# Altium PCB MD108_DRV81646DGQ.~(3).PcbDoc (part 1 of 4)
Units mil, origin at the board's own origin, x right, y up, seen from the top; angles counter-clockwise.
Board outline 6002 x 2931.52 mil, 4 copper layers (Top Layer, Mid-Layer 1, Mid-Layer 2, Bottom Layer), stack 92.712 mil thick; 255 components, 141 nets, 784 pads, 239 vias.
Unrouted connection lines stored in the file: 111.
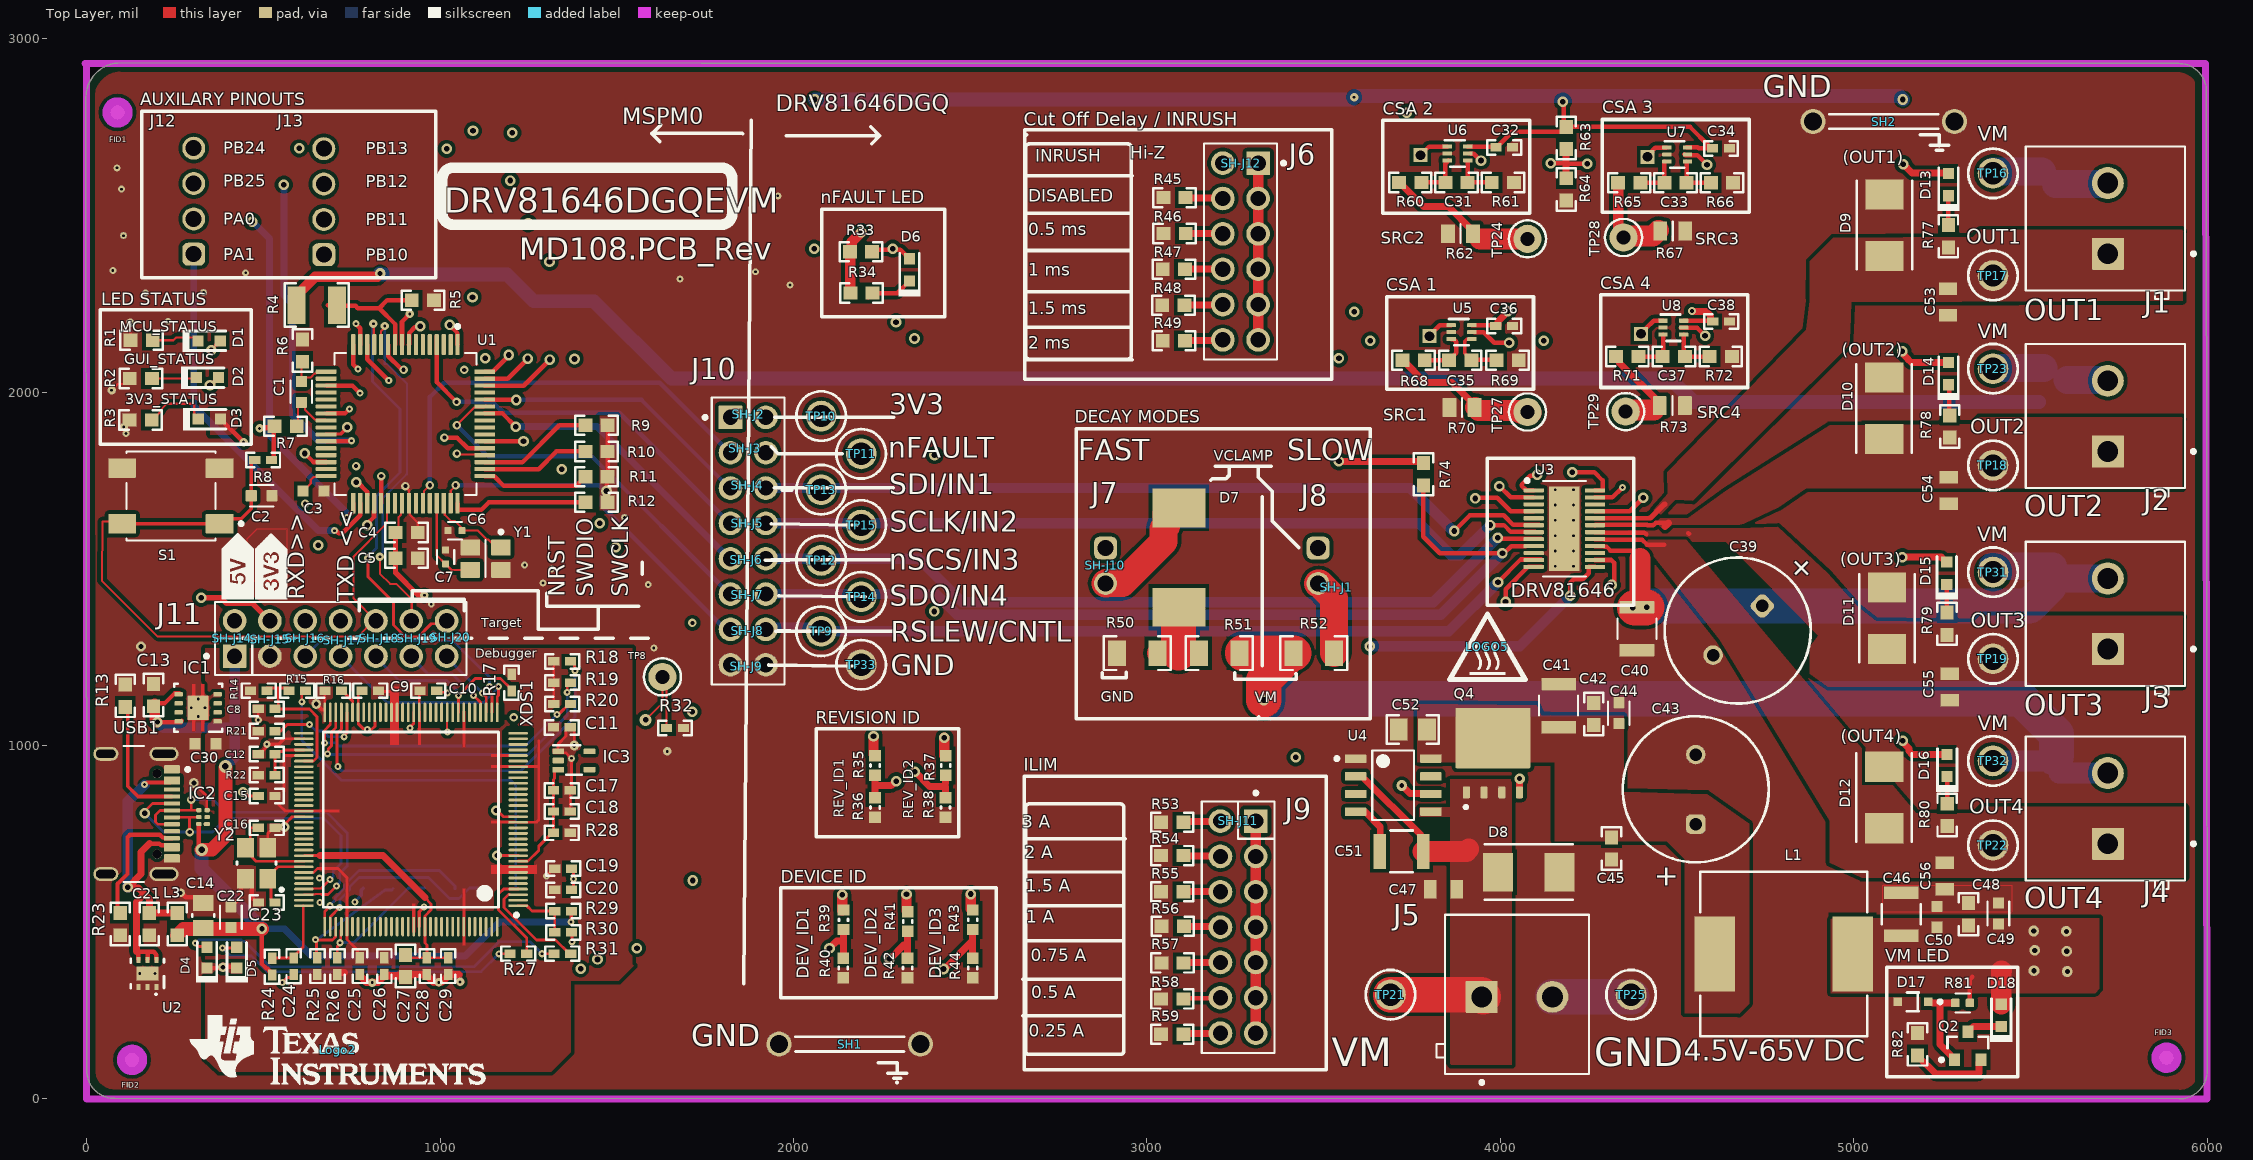
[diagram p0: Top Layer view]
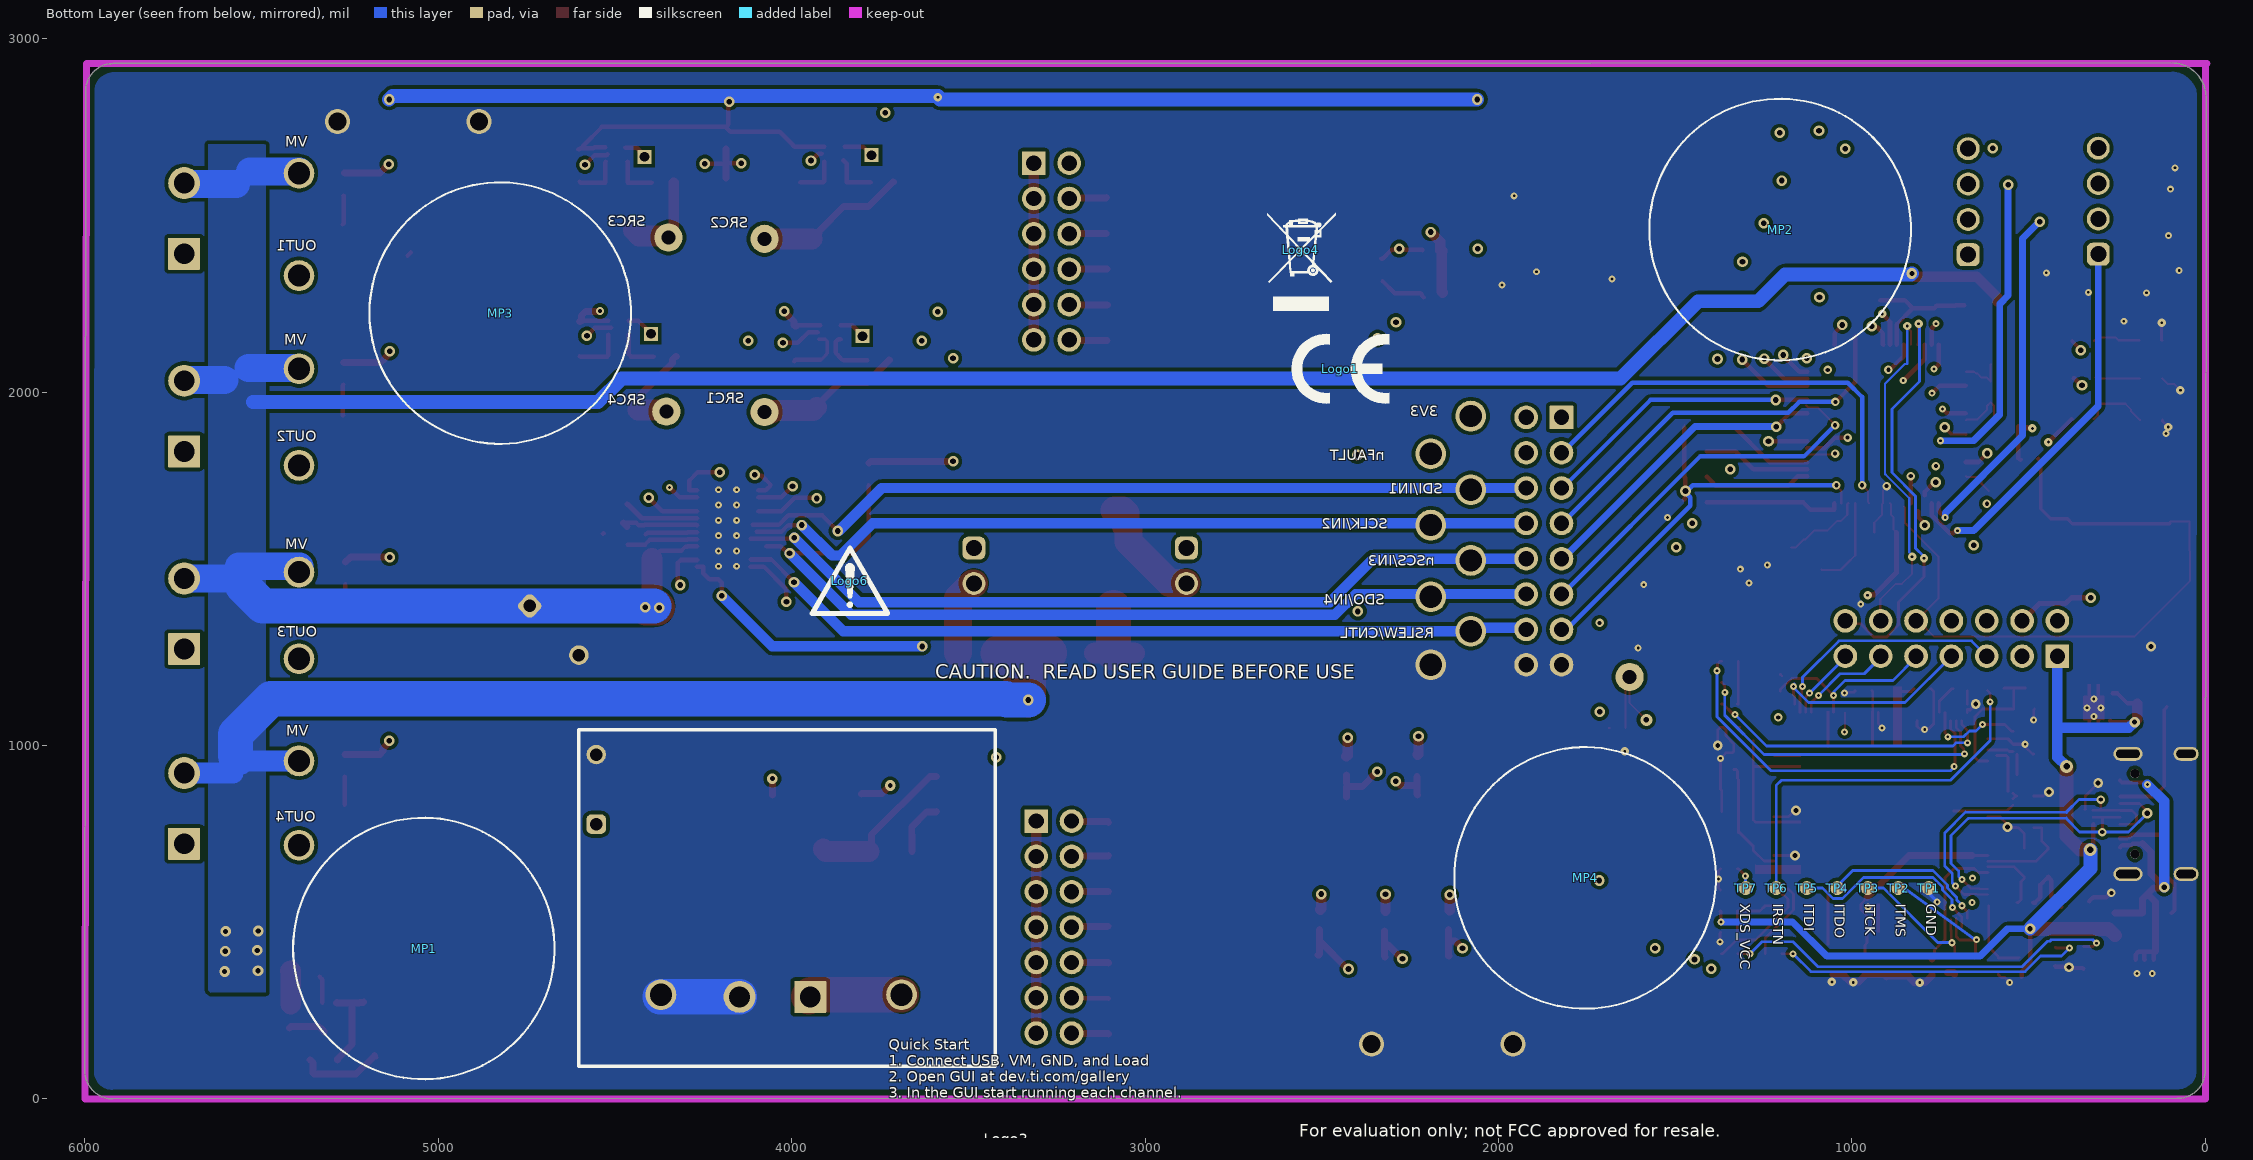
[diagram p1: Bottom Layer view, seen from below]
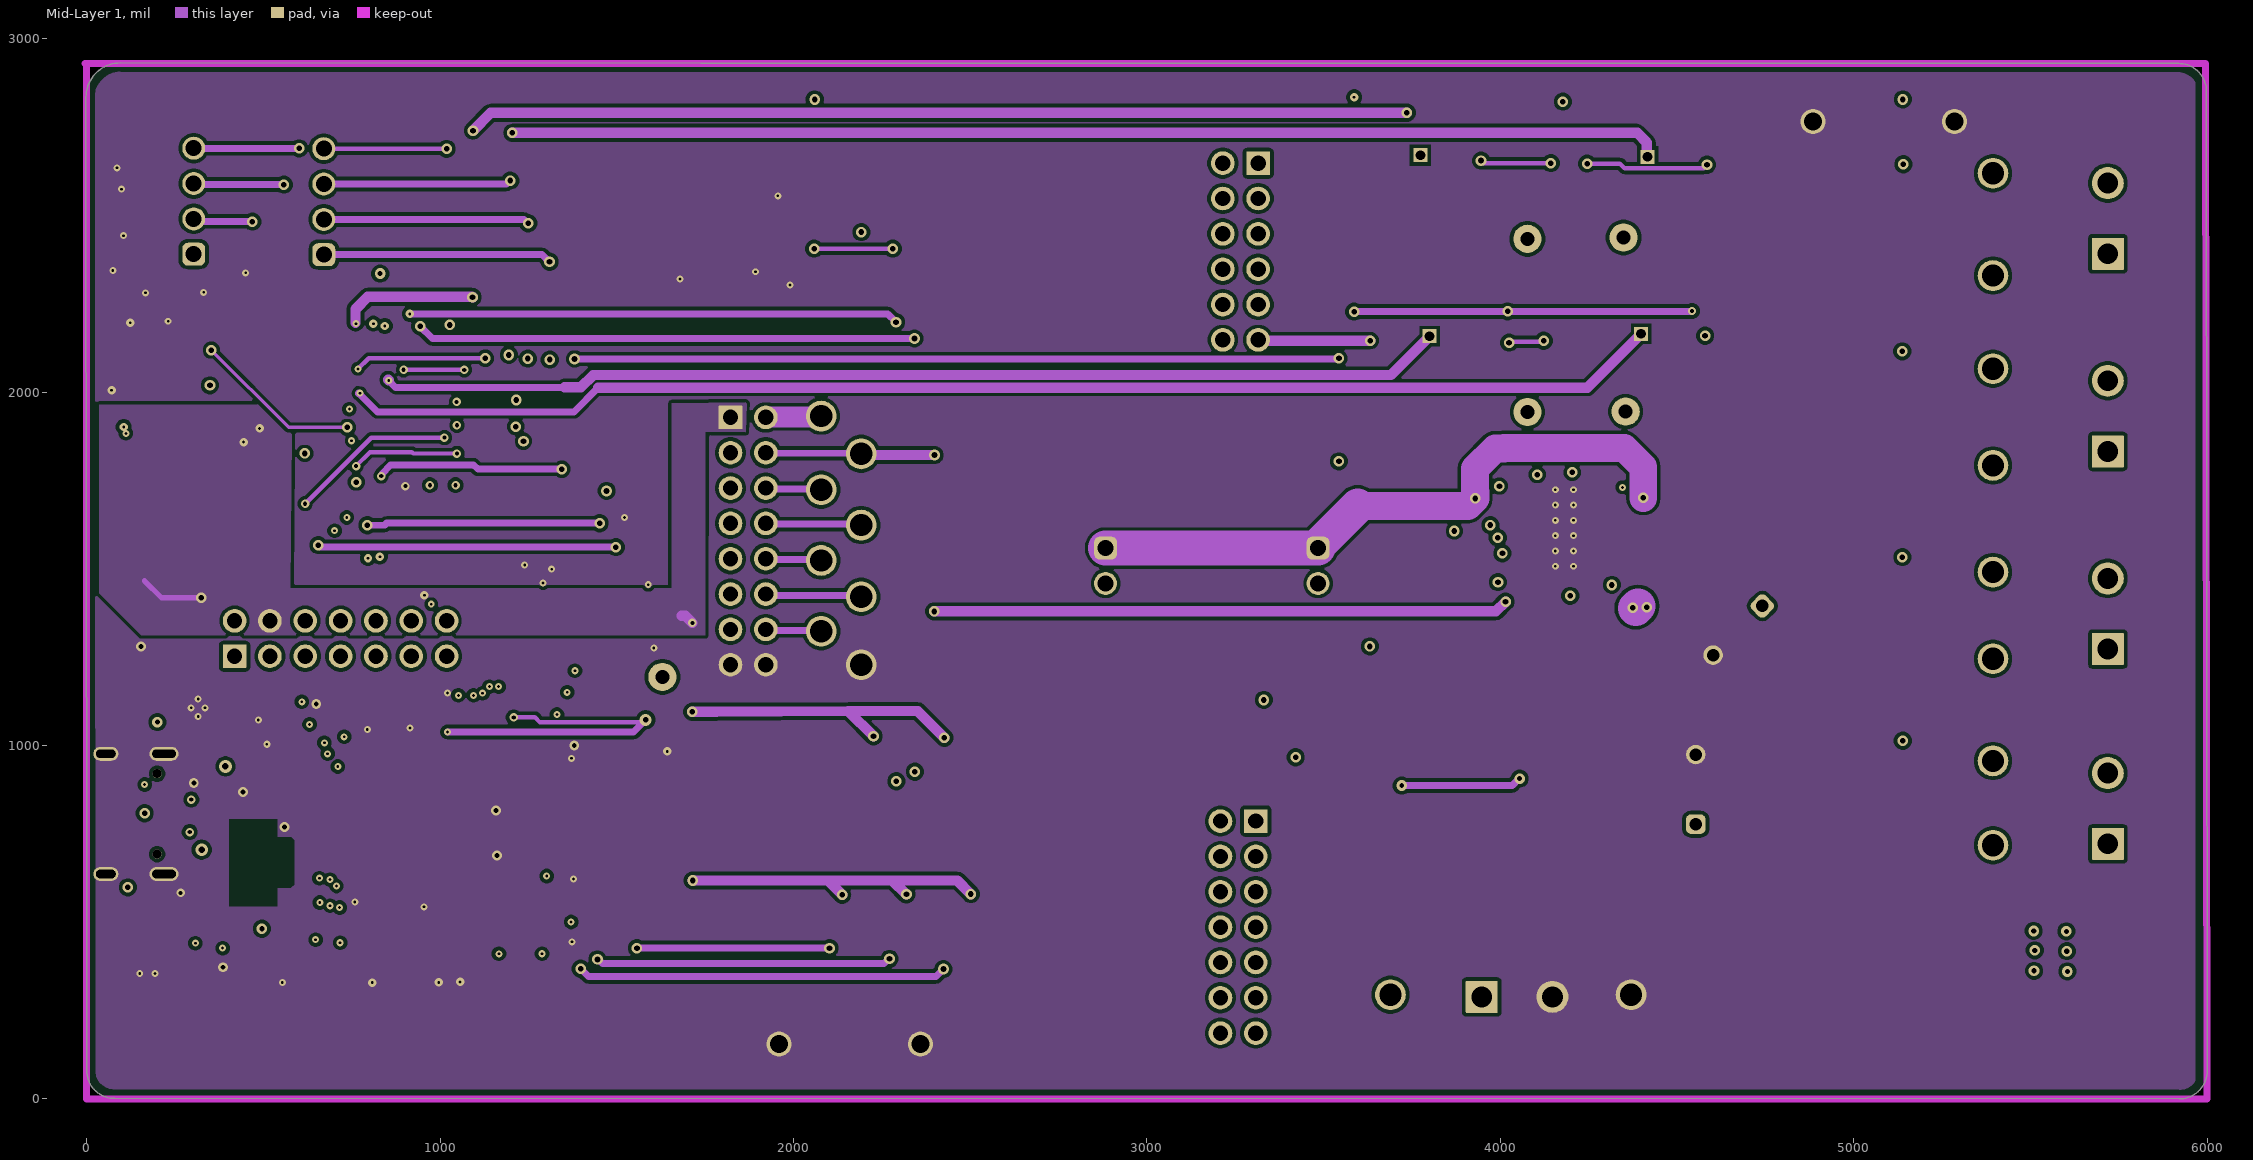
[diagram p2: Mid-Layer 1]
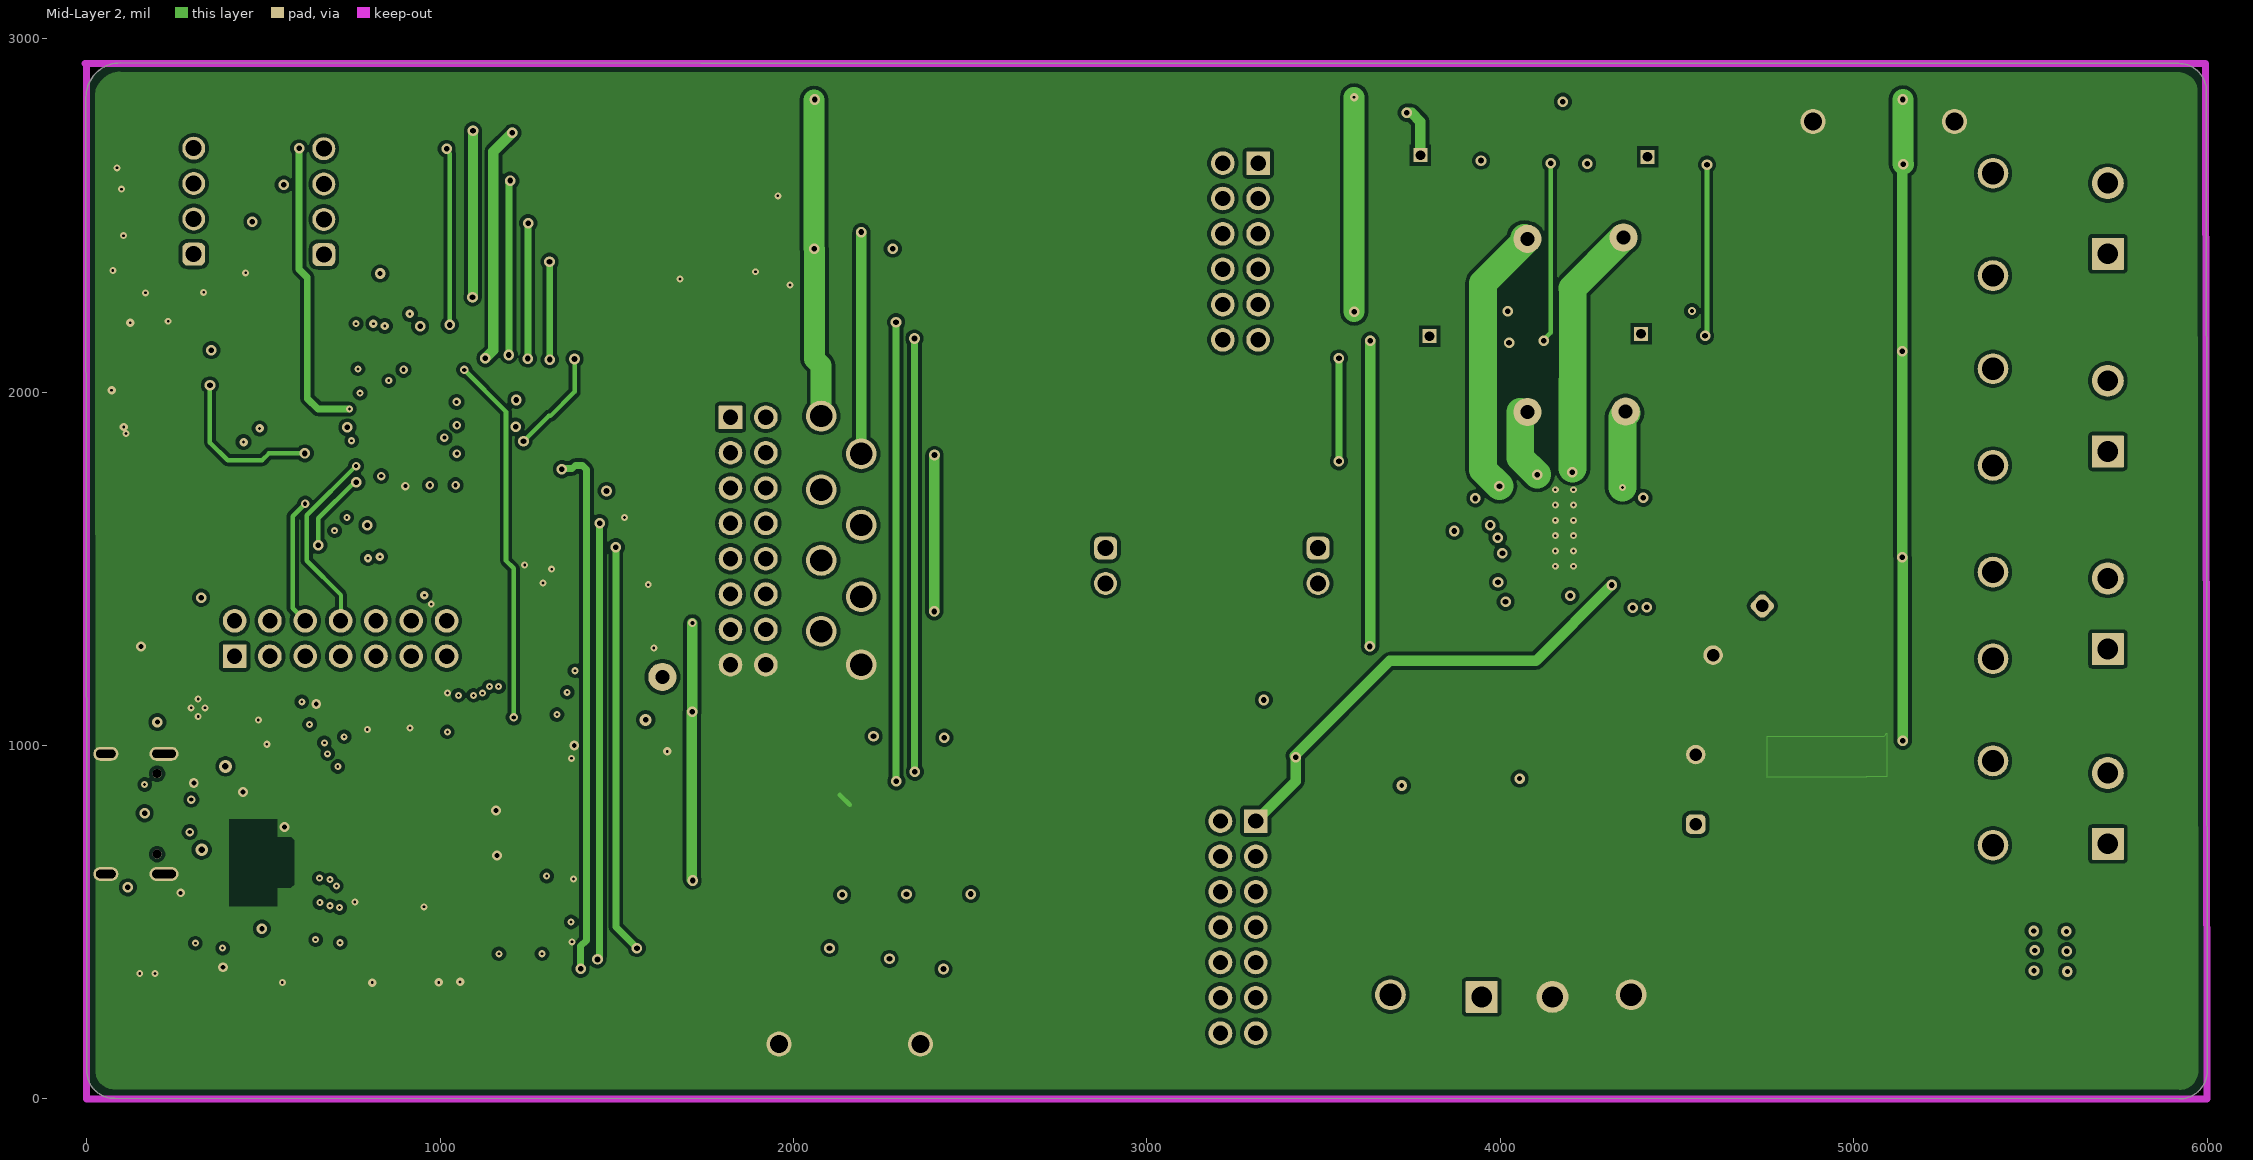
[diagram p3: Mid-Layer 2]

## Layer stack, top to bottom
Top Solder: solder mask 0.4, Solder Resist, Dk 3.5
Top Layer: signal copper 2.7559
Dielectric1: core 59.2, FR-4 High Tg, Dk 4.8
Mid-Layer 1: signal copper 1.4
Dielectric2: dielectric 12.6, FR-4, Dk 4.8
Mid-Layer 2: signal copper 1.4
Dielectric3: dielectric 12.6, FR-4, Dk 4.8
Bottom Layer: signal copper 2.7559
Bottom Solder: solder mask 0.4, Solder Resist, Dk 3.5

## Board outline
0,613.39 0,675.71 -2,2516.61 -2,2834.26 cw(c95.27,2834.26) 95.27,2931.53 1737.96,2930 5919.26,2930 cw(c5919.26,2851.26) 5998,2851.26 6000,78.76 cw(c5921.26,78.76) 5921.26,0.02 78.74,1.26 cw(c78.74,80) 0,80

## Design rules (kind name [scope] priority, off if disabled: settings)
AcuteAngle [All] p1: minimum=4.50000000000000E+0001 checktracksonly=FALSE
AssemblyTestPointUsage [All] p1: valid=2
BoardOutlineClearance BoardOutlineClearance_MountingHoles [OnCopper and InComponentClass('Mounting Holes')] p1: gap=15 ignorepadtopadclearanceinfootprint=FALSE
BoardOutlineClearance BoardOutlineClearance_Poly [OnCopper and IsPoly] p2: gap=25 ignorepadtopadclearanceinfootprint=FALSE
BoardOutlineClearance [OnCopper and Not InComponentClass('Logo') and not InComponentClass('FiducialMark') and not InRegion(1000,500,4000,800) and not InPoly] p3: gap=15 ignorepadtopadclearanceinfootprint=FALSE
Clearance Clearance_Keepouts [((IsTrack Or IsArc) And Not InPoly) And IsFree and IsKeepOut vs ((IsTrack Or IsArc) And Not InPoly) And IsFree and IsKeepOut] p1: gap=0 ignorepadtopadclearanceinfootprint=FALSE
Clearance Clearance_Poly [InPolygon] p2: gap=10 ignorepadtopadclearanceinfootprint=TRUE
Clearance Clearance_FiducialMark [IsKeepOut and InComponentClass('FiducialMark') vs IsPad and InComponentClass('FiducialMark')] p3: gap=0 ignorepadtopadclearanceinfootprint=TRUE
Clearance [All] p4: gap=6 ignorepadtopadclearanceinfootprint=TRUE
ComponentClearance ComponentClearance_Shunt [InComponentClass('Header') vs InComponentClass('Shunt')] p1: gap=0 collisioncheckmode=3 verticalgap=0 showdistances=FALSE
ComponentClearance ComponentClearance_PI_FILTER_R75 [InComponent('R75') vs InComponent('L1')] p2: gap=0 collisioncheckmode=3 verticalgap=0 showdistances=FALSE
ComponentClearance ComponentClearance_PI_FILTER_R66 [InComponent('R66') vs InComponent('L1')] p3: gap=0 collisioncheckmode=3 verticalgap=0 showdistances=FALSE
ComponentClearance ComponentClearance_CANL_Choke [InComponent('L2') vs InComponent('R71')] p4: gap=0 collisioncheckmode=3 verticalgap=0 showdistances=FALSE
ComponentClearance ComponentClearance_CANH_Choke [InComponent('L2') vs InComponent('R68')] p5: gap=0 collisioncheckmode=3 verticalgap=0 showdistances=FALSE
ComponentClearance ComponentClearance_MountingHoles_FiducialMarks [InComponentClass('Mounting Holes') vs InComponentClass('FiducialMark')] p6: gap=50 collisioncheckmode=3 verticalgap=10 showdistances=FALSE
ComponentClearance ComponentClearance_Logo [InComponentClass('Logo')] p7: gap=30 collisioncheckmode=3 verticalgap=10 showdistances=FALSE
ComponentClearance ComponentClearance_ScrewToNut [(HasFootprint('NY PMS 440 0025 PH')) vs (HasFootprint('Keystone_1902C'))] p8: gap=5 collisioncheckmode=3 verticalgap=10 showdistances=FALSE
ComponentClearance ComponentClearance_MountingHoles [InComponentClass('Mounting Holes')] p9: gap=100 collisioncheckmode=3 verticalgap=100000 showdistances=FALSE
ComponentClearance ComponentClearance_SmallPassives [HasFootprint('0201*') or HasFootprint('0402*') or HasFootprint('0508') or HasFootprint('0603*') or HasFootprint('0612') or HasFootprint('0805*') or HasFootprint('0815*') or HasFootprint('0830*') or HasFootprint('1206*') or HasFootprint('1210*') or HasFootprint('1808*') or HasFootprint('1812*') or HasFootprint('1825*') or HasFootprint('2010*') or HasFootprint('2220*') or HasFootprint('2225*') or HasFootprint('2512*') or HasFootprint('2728*') or HasFootprint('3518*') vs HasFootprint('0201*') or HasFootprint('0402*') or HasFootprint('0508') or HasFootprint('0603*') or HasFootprint('0612') or HasFootprint('0805*') or HasFootprint('0815*') or HasFootprint('0830*') or HasFootprint('1206*') or HasFootprint('1210*') or HasFootprint('1808*') or HasFootprint('1812*') or HasFootprint('1825*') or HasFootprint('2010*') or HasFootprint('2220*') or HasFootprint('2225*') or HasFootprint('2512*') or HasFootprint('2728*') or HasFootprint('3518*')] p10: gap=14.96 collisioncheckmode=3 verticalgap=10 showdistances=FALSE
ComponentClearance ComponentClearance_THtoSMT [IsThruComponent vs IsSMTComponent] p11: gap=30 collisioncheckmode=3 verticalgap=30 showdistances=FALSE
ComponentClearance ComponentClearance_THtoTH [IsThruComponent vs IsThruComponent] p12: gap=20 collisioncheckmode=3 verticalgap=30 showdistances=FALSE
ComponentClearance [All] p13: gap=20 collisioncheckmode=3 verticalgap=10 showdistances=FALSE
DiffPairsRouting [All] p1: maxlimit=100 minlimit=10 mostfreqgap=10 toplayer_minwidth=6 toplayer_maxwidth=15 toplayer_prefwidth=10 midlayer1_minwidth=6 midlayer1_maxwidth=15 midlayer1_prefwidth=10 midlayer2_minwidth=6 midlayer2_maxwidth=15 midlayer2_prefwidth=10 bottomlayer_minwidth=6 bottomlayer_maxwidth=15 bottomlayer_prefwidth=10 maxuncoupledlength=1000
FabricationTestPointUsage TestPointUsage [All] p1: valid=2 allowmultiple=FALSE
FabricationTestpoint Testpoint [All] p1: side=3 testpointundercomponent=TRUE minsize=40 maxsize=100 preferedsize=60 minholesize=0 maxholesize=40 preferedholesize=32 testpointgrid=1 allowsidetop=TRUE allowsidebottom=TRUE usegrid=TRUE gridtolerance=0.01
FanoutControl Fanout_LCC [IsLCC] p1: bgadir=Out bgaviamode=Centered fanoutstyle=Auto fanoutdirection=Alternating viagrid=1 // Fanout_LCC (Default Rule)
FanoutControl Fanout_BGA [IsBGA] p2: bgadir=Out bgaviamode=Centered fanoutstyle=Auto fanoutdirection=Alternating viagrid=1 // Fanout_BGA (Default Rule)
FanoutControl Fanout_Default [All] p4: bgadir=Out bgaviamode=Centered fanoutstyle=Auto fanoutdirection=Alternating viagrid=1 // Fanout_Default (Default Rule)
FanoutControl Fanout_Small [(CompPinCount < 5)] p5: bgadir=Out bgaviamode=Centered fanoutstyle=Auto fanoutdirection=OutThenIn viagrid=1 // Fanout_Small (Default Rule)
HoleSize [All] p1: absolutevalues=TRUE maxlimit=251 minlimit=7.87 maxpercent=80.000 minpercent=20.000
MinimumAnnularRing MinimumAnnularRing_ThermalPadVias [IsVia and InAnyComponent] p1: minimumring=5.91
MinimumAnnularRing [All] p2: minimumring=5.91
MinimumSolderMaskSliver MinimumSolderMaskSliver_Logo [InComponentClass('Logo') vs InComponentClass('Logo')] p1: minsoldermaskwidth=0.7
MinimumSolderMaskSliver [All] p2: minsoldermaskwidth=3.94
PlaneClearance [All] p1: clearance=10
PlaneConnect [All] p1: planeconnectstyle=Direct reliefexpansion=10 reliefentries=4 reliefconductorwidth=10 reliefairgap=10
PolygonConnect [All] p1: connectstyle=Direct reliefconductorwidth=10 reliefentries=4 polygonreliefangle="90 Angle" airgapwidth=10
RoutingVias ThermalPadVias [IsVia and InAnyComponent] p1: holewidth=7.87 width=19.68 viastyle="Through Hole" minholewidth=7.87 minwidth=19.68 maxholewidth=12.99 maxwidth=23.62
RoutingVias [All] p2: holewidth=16 width=34 viastyle="Through Hole" minholewidth=7.87 minwidth=19.68 maxholewidth=236.22 maxwidth=236.22
SilkToBoardRegionClearance [Not ((IsComment or IsDesignator) And (Hide <> 'False')) and not InRegion(1000,500,4000,800)] p1:
SilkToSilkClearance SilkToSilkClearance_Pb-FreeLogo [(HasFootprint('Pb-Free_Overlay_Medium') OR HasFootprint('Pb-Free_Overlay_Small')) vs (HasFootprint('Pb-Free_Overlay_Medium') OR HasFootprint('Pb-Free_Overlay_Small'))] p1: silktosilkclearance=0
SilkToSilkClearance [All] p2: silktosilkclearance=3.94
SilkToSolderMaskClearance SilkToComponentPadClearance [(IsPad or IsFill or IsRegion) and InAnycomponent] p1: minsilkscreentomaskgap=5 clearancetoexposedcopper=TRUE
SilkToSolderMaskClearance "Silk to Solder Mask Opening" [All] p2: minsilkscreentomaskgap=3.94 clearancetoexposedcopper=FALSE
SolderMaskExpansion [All] p1: expansion=1.97 istentingtop=FALSE
UnRoutedNet [All] p1: checkbadconnections=TRUE
Width [All] p1: maxlimit=100 minlimit=6 preferedwidth=10 checkconnectedcopper=TRUE
13 further rules are at their usual default settings.

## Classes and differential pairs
component class MD108_DRV81646_ADC: C31 C32 C33 C34 C35 C36 C37 C38 R60 R61 R63 R64 R65 R66 R68 R69 R71 R72 U5 U6 U7 U8
component class MD108_DRV81646__Hardware: !PCB1 FID1 FID2 FID3 Logo1 Logo2 Logo3 Logo4 LOGO5 Logo6 MP1 MP2 MP3 MP4 ZZ1 ZZ2 ZZ3 ZZ4
component class MD108_DRV81646: 15 C39 C40 C41 C42 C43 C44 C45 C46 C47 C48 C49 C50 C51 C52 C53 C54 C55 C56 D7 D8 D9 D10 D11 D12 D13 D14 D15 D16 J1 J2 J3 J4 J5 J6 J7 J8 J9 L1 L? Q4 R45 R46 R47 R48 R49 R50 R51 R52 R53 R54 R55 R56 R57 R58 R59 R62 R67 R70 R73 R77 R78 R79 R80 SH1 SH2 SH-J1 SH-J10 SH-J11 SH-J12 TP16 TP17 TP18 TP19 TP21 TP22 TP23 TP24 TP25 TP27 TP28 TP29 TP31 TP32 U3 U4
component class MD108_DRV81646_XDS110: C8 C9 C10 C11 C12 C13 C14 C15 C16 C17 C18 C19 C20 C21 C22 C23 C24 C25 C26 C27 C28 C29 C30 D4 D5 IC1 IC2 IC3 J11 L3 R13 R14 R15 R16 R17 R18 R19 R20 R21 R22 R23 R24 R25 R26 R27 R28 R29 R30 R31 SH-J14 SH-J15 SH-J16 SH-J17 SH-J18 SH-J19 SH-J20 TP1 TP2 TP3 TP4 TP5 TP6 TP7 U2 USB1 XDS1 Y2
component class MD108_DRV81646_M0: 20 C1 C2 C3 C4 C5 C6 C7 D1 D2 D3 D6 D17 D18 J10 J12 J13 Q2 R1 R2 R3 R4 R5 R6 R7 R8 R9 R10 R11 R12 R32 R33 R34 R35 R36 R37 R38 R39 R40 R41 R42 R43 R44 R74 R81 R82 S1 SH-J2 SH-J3 SH-J4 SH-J5 SH-J6 SH-J7 SH-J8 SH-J9 TP8 TP9 TP10 TP11 TP12 TP13 TP14 TP15 TP33 U1 Y1
differential pair XDS_USB_D: +XDS_USB_D_P -XDS_USB_D_N

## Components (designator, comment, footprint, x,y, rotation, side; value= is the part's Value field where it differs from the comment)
C1 "885012206126" FP-885012206126_0603-MFG 607.41,2000.55 r270 top value=1µF
C2 "885012206065" FP-885012206065_0603-MFG 495.05,1706.73 r0 top value=10nF
C3 "885012206075R" WCAP-CSGP_0603_L1.6W0.8H0.8_Reflow 642.05,1720 r180 top value=470nF
C4 "885012206095" 0603 905.33,1602.89 r0 top value=0.1uF
C5 "GRM188R61E106KA73D" 0603 905.33,1530 r0 top value=10uF
C6 "885012005057" FP-885012005057_0402-MFG 1042.39,1607.9 r0 top value=22pF
C7 "885012005057" FP-885012005057_0402-MFG 1015.46,1533.37 r270 top value=22pF
C8 "GRM155R70J104KA01D" 0402 509,1103.54 r180 top value=0.1uF
C9 "GRM155R71E103KA01D" 0402 802.37,1154.97 r180 top value=0.01uF
C10 "GRM155R71E103KA01D" 0402 966.81,1154.97 r0 top value=0.01uF
C11 "GRM155R71E103KA01D" 0402 1344.73,1051.55 r0 top value=0.01uF
C12 "GRM155R70J104KA01D" 0402 509,975.59 r180 top value=0.1uF
C13 "885012206052" 0603 189.03,1142.53 r90 top value=1uF
C14 "885012107014" 0805_150 329.91,519.42 r90 top value=10uF
C15 "GRM155R71E103KA01D" 0402 509,857.18 r180 top value=0.01uF
C16 "GRM1555C1H120JA01D" 0402 509,767.24 r0 top value=12pF
C17 "GRM155R70J104KA01D" 0402 1344.73,873 r0 top value=0.1uF
C18 "GRM155R71E103KA01D" 0402 1344.73,813.04 r0 top value=0.01uF
C19 "C1005X5R1E105K050BC" 0402 1348.19,651.39 r0 top value=1uF
C20 "GRM155R70J104KA01D" 0402 1348.19,591.43 r0 top value=0.1uF
C21 "885012206089" 0603 177.25,494.57 r270 top value=0.01uF
C22 "885012206095" FP-885012206095_0603-MFG 408.25,514.37 r90 top value=100nF
C23 "GRM1555C1H120JA01D" 0402 509.41,555.64 r180 top value=12pF
C24 "GRM155R70J104KA01D" 0402 585.83,375.41 r270 top value=0.1uF
C25 "GRM155R70J104KA01D" 0402 773.12,375.96 r270 top value=0.1uF
C26 "C1005X5R1E105K050BC" 0402 842,375.96 r270 top value=1uF
C27 "C0603C225K8PACTU" 0603 902.34,375.96 r270 top value=2.2uF
C28 "GRM155R70J104KA01D" 0402 962.68,375.96 r270 top value=0.1uF
C29 "C1005X5R1E105K050BC" 0402 1023.03,375.96 r270 top value=1uF
C30 "885012206027" WCAP-CSGP_0603_L1.6W0.8H0.8_Reflow 336.05,1004.81 r0 top
C31 "885012206046" 0603 3876.1,2593.45 r0 top value=0.1uF
C32 "885012105001" 0402 4011.06,2692.55 r180 top value=0.1uF
C33 "885012206046" 0603 4495.61,2592.62 r0 top value=0.1uF
C34 "885012105001" 0402 4624.49,2689.56 r180 top value=0.1uF
C35 "885012206046" 0603 3886.74,2090.28 r0 top value=0.1uF
C36 "885012105001" 0402 4010.62,2187.16 r180 top value=0.1uF
C37 "885012206046" 0603 4491.03,2100.6 r0 top value=0.1uF
C38 "885012105001" 0402 4624.72,2199.69 r180 top value=0.1uF
C39 "860040875002" WCAP-ATUL_D10H12.5 4671.79,1325.24 r45 top
C40 "885012209069" FP-885012209069_1210-MFG 4386.53,1330.37 r90 top value=1µF
C41 "885012209069" FP-885012209069_1210-MFG 4165.2,1112.91 r270 top value=1µF
C42 "885012206114" 0603 4264.44,1089.02 r270 top value=0.01uF
C43 "860040875004" WCAP-ATUL_D10H20 4553.07,876 r270 top
C44 "885012206120" FP-885012206120_0603-MFG 4335.44,1091.54 r270 top value=100nF
C45 "06031C102KAT2A" 0603 4314.68,708.6 r270 top value=1000pF
C46 "885012209069" FP-885012209069_1210-MFG 5134.6,522.48 r270 top value=1µF
C47 "885012207124" WCAP-CSGP_0805_L2W1.25H0.8_Reflow 3839.36,593.25 r0 top
C48 "885012206114" 0603 5324.84,522.48 r270 top value=0.01uF
C49 "885012206120" FP-885012206120_0603-MFG 5409.61,524.35 r270 top value=100nF
C50 "885012206108" WCAP-CSGP_0603_L1.6W0.8H0.8_Reflow 5236.17,515.12 r270 top
C51 "885382209002" WCAP-CSST_1210_L3.2W2.5H2.5 3720.55,700.46 r0 top
C52 "C2012X7S2A105K125AB" 0805_HV 3752.39,1045.6 r180 top value=1uF
C53 "885012207124" WCAP-CSGP_0805_L2W1.25H0.8_Reflow 5267.21,2255.09 r90 top
C54 "885012207124" WCAP-CSGP_0805_L2W1.25H0.8_Reflow 5268.84,1721.22 r90 top
C55 "885012207124" WCAP-CSGP_0805_L2W1.25H0.8_Reflow 5271.77,1165.87 r90 top
C56 "885012207124" WCAP-CSGP_0805_L2W1.25H0.8_Reflow 5257.62,630.82 r90 top
D1 "150060VS75000" WL-SMCW_GREEN 346.32,2145.05 r0 top value=Green
D2 "150060VS75000" WL-SMCW_GREEN 341.42,2040.9 r0 top value=Green
D3 "150060VS75000" WL-SMCW_GREEN 347.02,1923.54 r0 top value=Green
D4 "LTST-C190KRKT" LED_LTST-C190_Red 340.61,399.58 r270 top value=Red
D5 "LTST-C190GKT" LED_LTST-C190 424.61,399.58 r270 top value=Green
D6 "150060RS75000" WL-SMCW_RED 2328.08,2345.76 r90 top value=Red
D7 "SMCJ33CA" SMC_Bi 3090.32,1531.78 r270 top value=33V
D8 "SMBJ70CA-13-F" SMB-Bi 4080.57,641.49 r180 top value=70V
D9 "SMBJ33CA-13-F" SMB-Bi 5087.03,2472.52 r270 top value=33V
D10 "SMBJ33CA-13-F" SMB-Bi 5086.38,1954.04 r270 top value=33V
D11 "SMBJ33CA-13-F" SMB-Bi 5093.88,1359.86 r270 top value=33V
D12 "SMBJ33CA-13-F" SMB-Bi 5086.38,852.82 r270 top value=33V
D13 "150060VS75000" WL-SMCW_GREEN 5268.29,2587.26 r90 top value=Green
D14 "150060VS75000" WL-SMCW_GREEN 5268.47,2052.36 r90 top value=Green
D15 "150060VS75000" WL-SMCW_GREEN 5263.45,1487.42 r90 top value=Green
D16 "150060VS75000" WL-SMCW_GREEN 5264.42,943.52 r90 top value=Green
D17 "BZX84J-B4V7,115" FP-SOD323F-MFG 5167.62,274.75 r180 top
D18 "150060VS75000" WL-SMCW_GREEN 5417.46,236.37 r90 top value=Green
FID1 "Fiducial" Fiducial10-20 87.36,2791.28 r0 top
FID2 "Fiducial" Fiducial10-20 128.19,110.46 r0 top
FID3 "Fiducial" Fiducial10-20 5884.93,116.59 r0 top
IC1 "TPS73533DRBT" DRB0008A 315.39,1106.58 r180 top
IC2 "TPD4E004DRYR" DRY0006A 329.16,797.26 r180 top
IC3 "LM4040C25IDCKR" DCK0005A_N 1378.61,957.57 r0 top
J1 "691236510002" FP-691236510002_HHR2-MFG 5712.13,2479.6 r90 top
J2 "691236510002" FP-691236510002_HHR2-MFG 5712.13,1920.23 r90 top
J3 "691236510002" FP-691236510002_HHR2-MFG 5712.13,1360.87 r90 top
J4 "691236510002" FP-691236510002_HHR2-MFG 5712.13,810.06 r90 top
J5 "691236510002" FP-691236510002_HHR2-MFG 4035.69,295.59 r0 top
J6 "61301221121" FP-61301221121_HDR12-MFG 3264.82,2397.78 r270 top
J7 "61300211121" WURTH_61300211121 2883.02,1508.7 r270 top
J8 "61300211121" WURTH_61300211121 3484.34,1508.63 r270 top
J9 "61301421121" FP-61301421121_HDR14-MFG#1 3258.12,486.13 r270 top
J10 "61301621121" FP-61301621121_HDR16-MFG 1871.74,1578.5 r270 top
J11 "61301421121" FP-61301421121_HDR14-MFG#2 718.44,1302.72 r0 top locked
J12 "61300411121" WURTH_61300411121 302.88,2540.15 r90 top
J13 "61300411121" WURTH_61300411121 670.89,2538.76 r90 top
L1 "7443320100" WE-HCC_1210 4802.03,410.11 r0 top value=1uH
L3 "742863160" 0603 256.06,494.57 r270 top value="600 ohm"
Logo1 "CE Mark" CE_Mark_5mm 2447.5,2066.02 r180 bottom
Logo2 "Texas Instruments" TI_Stacked_Overlay_Small 710.1,138.81 r0 top
Logo3 "FCC disclaimer" FCC_disclaimer -705,1946.08 r90 bottom
Logo4 "WEEE logo" WEEE_Minimum 2559.23,2402.87 r180 bottom
LOGO5 "CAUTION HOT SURFACE" IEC_HotSurface_Small 3963.77,1279.84 r0 top
Logo6 "CAUTION.  READ USER GUIDE BEFORE USE" IEC_Caution_Small 3835.17,1466.27 r180 bottom
MP1 "RBS-37BK" FP-RBS-37BK_BUMPER_CYLI-MFG 5041.03,425.57 r180 bottom
MP2 "RBS-37BK" FP-RBS-37BK_BUMPER_CYLI-MFG 1203.08,2460 r180 bottom
MP3 "RBS-37BK" FP-RBS-37BK_BUMPER_CYLI-MFG 4824.79,2223.61 r180 bottom
MP4 "RBS-37BK" FP-RBS-37BK_BUMPER_CYLI-MFG 1754.91,625.3 r180 bottom
Q2 "BC846BLT1G" ONSC-SOT-23-3-318-08_V 5323.01,150.05 r90 top
Q4 "CSD19502Q5B" DNK0008A 3979.19,978.27 r90 top value=80V
R1 "RC0603JR-07330RL" 0603 155.3,2146.65 r0 top value=330
R2 "RC0603JR-07330RL" 0603 153.23,2038.49 r0 top value=330
R3 "RC0603JR-07330RL" 0603 152.54,1921.12 r0 top value=330
R4 "RC1210JR-0720KL" 1210 650.95,2246.08 r180 top value=20k
R5 "RC0603JR-071KL" 0603 951.19,2259.83 r180 top value=1.0k
R6 "Resistor" 0603 610.38,2117.27 r270 top value=0
R7 "Resistor" 0603 562.84,1903.13 r0 top value=0
R8 "CRCW040247K0JNED" 0402 498.96,1808.03 r0 top value=47k
R9 "ERJ-3GEYJ104V" 0603 1442.48,1906.07 r0 top value=100k
R10 "RC0603FR-07249KL" 0603 1442.48,1832.03 r0 top value=249k
R11 "RC0603FR-0744K2L" 0603 1442.48,1760.56 r0 top value=44.2k
R12 "RC0603FR-0714KL" 0603 1442.48,1688.28 r0 top value=14.0k
R13 "RC0603JR-075K1L" 0603 108.91,1140.63 r90 top value=5.1k
R14 "CRCW040210K0JNED" 0402 486.88,1154.97 r180 top value=10k
R15 "CRCW0402100RJNED" 0402 595.6,1154.97 r180 top value=100
R16 "CRCW04024K87FKED" 0402 697.67,1154.97 r0 top value=4.87k
R17 "ERJ-2RKF3301X" 0402 1202.57,1177.91 r90 top value=3.30k
R18 "CRCW04021K00JNED" 0402 1345.19,1238.25 r180 top value=1.0k
R19 "CRCW04021K00JNED" 0402 1345.19,1177.91 r180 top value=1.0k
R20 "CRCW04021K00JNED" 0402 1345.19,1117.57 r180 top value=1.0k
R21 "CRCW04021K00JNED" 0402 509,1040.68 r180 top value=1.0k
R22 "CRCW040251R0JNED" 0402 509,916.14 r180 top value=51
R23 "RC0603JR-075K1L" 0603 94.73,494.57 r270 top value=5.1k
R24 "CRCW0402100RJNED" 0402 524.7,374.36 r90 top value=100
R25 "CRCW040210K0JNED" 0402 652.61,375.94 r90 top value=10k
R26 "CRCW040210K0JNED" 0402 709.08,375.96 r90 top value=10k
R27 "CRCW0402470RJNED" 0402 1221.5,410.78 r0 top value=470
R28 "CRCW04021K00JNED" 0402 1344.73,753.08 r0 top value=1.0k
R29 "RC0402FR-07330KL" 0402 1348.19,531.47 r180 top value=330k
R30 "RC0402FR-07220KL" 0402 1348.19,471.51 r180 top value=220k
R31 "CRCW0402470RJNED" 0402 1346.07,410.78 r0 top value=470
R32 "CRCW040247K0JNED" 0402 1664.63,1049.62 r180 top value=47k
R33 "RC0603FR-074K99L" 0603 2190.93,2397.03 r0 top value=4.99k
R34 "RC0603JR-07330RL" 0603 2192.28,2280.1 r0 top value=330
R35 "RC0603JR-0710KL" 0603L 2230.96,943.45 r270 top value=10k
R36 "RC0603JR-0710KL" 0603L 2230.96,824.68 r270 top value=10k
R37 "RC0603JR-0710KL" 0603L 2430.64,943.45 r270 top value=10k
R38 "RC0603JR-0710KL" 0603L 2430.05,824.68 r270 top value=10k
R39 "RC0603JR-0710KL" 0603L 2141.22,506.62 r270 top value=10k
R40 "RC0603JR-0710KL" 0603L 2140.92,370.32 r270 top value=10k
R41 "RC0603JR-0710KL" 0603L 2323.2,502.09 r270 top value=10k
R42 "RC0603JR-0710KL" 0603L 2323.04,370.32 r270 top value=10k
R43 "RC0603JR-0710KL" 0603L 2506.99,506.62 r270 top value=10k
R44 "RC0603JR-0710KL" 0603L 2506.99,370.32 r270 top value=10k
R45 "RC0603FR-0710KL" 0603 3078.09,2550.3 r0 top value=10.0k
R46 "RC0603FR-0760K4L" 0603 3078.39,2449.01 r0 top value=60.4k
R47 "RC0603FR-07120KL" 0603 3076.26,2347.62 r0 top value=120k
R48 "RC0603FR-07180KL" 0603 3074.89,2246.05 r0 top value=180k
R49 "RC0603FR-07240KL" 0603 3076.26,2145.4 r0 top value=240k
R50 "CRCW12060000Z0EAHP" 1206 2972.91,1261.31 r0 top value=0
R51 "CRCW12060000Z0EAHP" 1206 3204.66,1261.31 r0 top value=0
R52 "CRCW12060000Z0EAHP" 1206 3472.19,1261.31 r180 top value=0
R53 "RC0603FR-0710KL" 0603 3071.69,782.73 r0 top value=10.0k
R54 "RC0603FR-0730KL" 0603 3071.69,688.45 r0 top value=30.0k
R55 "RC0603FR-0740K2L" 0603 3071.69,586.38 r0 top value=40.2k
R56 "RC0603FR-0760K4L" 0603 3073.17,488.58 r0 top value=60.4k
R57 "RC0603FR-0780K6L" 0603 3072.24,384.93 r0 top value=80.6k
R58 "RC0603FR-07120KL" 0603 3071.69,283.06 r0 top value=120k
R59 "RC0603FR-07240KL" 0603 3071.69,183.06 r0 top value=240k
R60 "ERJ-3GEY0R00V" 0603 3745.11,2593.39 r0 top value=0
R61 "ERJ-3GEY0R00V" 0603 4007.19,2593.45 r180 top value=0
R62 "580060720008" FP-580060720008_0805-MFG 3887.13,2448.16 r0 top value=10m
R63 "RC0603FR-07200RL" 0603 4186.49,2718.83 r90 top value=200
R64 "RC0603FR-07200RL" 0603 4186.49,2573.68 r90 top value=200
R65 "ERJ-3GEY0R00V" 0603 4364.97,2592.62 r0 top value=0
R66 "ERJ-3GEY0R00V" 0603 4627.42,2592.68 r180 top value=0
R67 "580060720008" FP-580060720008_0805-MFG 4487.92,2456.06 r180 top value=10m
R68 "ERJ-3GEY0R00V" 0603 3754.69,2090.21 r0 top value=0
R69 "ERJ-3GEY0R00V" 0603 4020.73,2090.28 r180 top value=0
R70 "580060720008" FP-580060720008_0805-MFG 3891.95,1956.14 r0 top value=10m
R71 "ERJ-3GEY0R00V" 0603 4359.37,2100.53 r0 top value=0
R72 "ERJ-3GEY0R00V" 0603 4623.9,2100.6 r180 top value=0
R73 "580060720008" FP-580060720008_0805-MFG 4486.7,1961.6 r180 top value=10m
R74 "RC0603FR-0710KL" 0603 3782.47,1767.52 r90 top value=10.0k
R77 "RC0603JR-07430RL" 0603 5267.95,2441.05 r90 top value=430
R78 "RC0603JR-07430RL" 0603 5271.63,1902.5 r90 top value=430
R79 "RC0603JR-07430RL" 0603 5263.97,1344.47 r90 top value=430
R80 "RC0603JR-07430RL" 0603 5264.42,803.75 r90 top value=430
R81 "RCC040247K0FKED" FP-RCC040247K0FKED_0402-MFG 5308.17,271.59 r0 top value=47k
R82 "RC0603FR-07470RL" 0603 5180.71,154.48 r270 top value=470
S1 "430481025816" FP-430481025816_SMT_SW_6MM2_6MM2-MFG 238.32,1706.39 r180 top
SH1 "Jumper_2p" Harwin_D3082-05 2159,154.99 r180 top
SH2 "Jumper_2p" Harwin_D3082-05 5085.01,2765.61 r180 top
SH-J1 "60900213421" Wurth_60900213421 3535.96,1448.43 r180 top
SH-J2 "60900213421" Wurth_60900213421 1871.63,1938.04 r180 top
SH-J3 "60900213421" Wurth_60900213421 1862.63,1841.54 r180 top
SH-J4 "60900213421" Wurth_60900213421 1868.77,1737.07 r180 top
SH-J5 "60900213421" Wurth_60900213421 1868.77,1629.54 r180 top
SH-J6 "60900213421" Wurth_60900213421 1865.7,1525.07 r180 top
SH-J7 "60900213421" Wurth_60900213421 1868.77,1426.75 r180 top
SH-J8 "60900213421" Wurth_60900213421 1868.77,1325.36 r180 top
SH-J9 "60900213421" Wurth_60900213421 1865.7,1223.97 r180 top
SH-J10 "60900213421" Wurth_60900213421 2882.46,1509.96 r270 top
SH-J11 "60900213421" Wurth_60900213421 3258.01,786.45 r180 top
SH-J12 "60900213421" Wurth_60900213421 3266.5,2647.22 r0 top
SH-J14 "60900213421" Wurth_60900213421 412.41,1303.85 r270 top
SH-J15 "60900213421" Wurth_60900213421 519.95,1300.78 r270 top
SH-J16 "60900213421" Wurth_60900213421 618.27,1303.85 r270 top
SH-J17 "60900213421" Wurth_60900213421 725.81,1297.71 r270 top
SH-J18 "60900213421" Wurth_60900213421 827.2,1303.85 r270 top
SH-J19 "60900213421" Wurth_60900213421 934.74,1303.85 r270 top
SH-J20 "60900213421" Wurth_60900213421 1029.98,1306.93 r270 top
TP1 "TESTPOINT" TP_SM_1MM 782.61,596.57 r180 bottom
TP2 "TESTPOINT" TP_SM_1MM 868.95,596.57 r180 bottom
TP3 "TESTPOINT" TP_SM_1MM 955.28,596.57 r180 bottom
TP4 "TESTPOINT" TP_SM_1MM 1041.61,596.57 r180 bottom
TP5 "TESTPOINT" TP_SM_1MM 1127.95,596.57 r180 bottom
TP6 "TESTPOINT" TP_SM_1MM 1214.28,596.57 r180 bottom
TP7 "TESTPOINT" TP_SM_1MM 1300.61,596.57 r180 bottom
TP8 "5002" Keystone5002 1629,1194 r90 top
TP9 "5012" Keystone5012 2078.24,1323.12 r90 top
TP10 "5013" Keystone5013 2078.24,1932.21 r90 top
TP11 "5012" Keystone5012 2191.45,1825.2 r90 top
TP12 "5012" Keystone5012 2078.24,1523.57 r90 top
TP13 "5012" Keystone5012 2078.24,1724.03 r90 top
TP14 "5012" Keystone5012 2191.45,1420.6 r90 top
TP15 "5012" Keystone5012 2191.45,1623.8 r90 top
TP16 "5010" Keystone5010 5394.16,2618.94 r270 top
TP17 "5012" Keystone5012 5394.16,2329.77 r270 top
TP18 "5012" Keystone5012 5394.16,1792.45 r270 top
TP19 "5012" Keystone5012 5394.16,1245.29 r270 top
TP21 "5010" Keystone5010 3689.25,294.92 r90 top
TP22 "5012" Keystone5012 5394.16,717.89 r270 top
TP23 "5010" Keystone5010 5394.16,2066.42 r270 top
TP24 "5002" Keystone5002 4076.86,2433.69 r90 top
TP25 "5011" Keystone5011 4370.1,294.92 r90 top
TP27 "5002" Keystone5002 4076.86,1943.72 r90 top
TP28 "5002" Keystone5002 4348.72,2437.5 r270 top
TP29 "5002" Keystone5002 4354.75,1944.92 r90 top
TP31 "5010" Keystone5010 5394.16,1490.69 r90 top
TP32 "5010" Keystone5010 5394.16,956.25 r90 top
TP33 "5011" Keystone5011 2191.45,1228.39 r90 top
U1 "MSPM0G3507SPM" PM0064A-MFG 902.05,1910 r270 top
U2 "TVS0500DRVR" DRV0006A 171.8,354.86 r90 top
U3 "DRV81646DGQ" DGQ0024A-MFG 4181.31,1613.52 r0 top
U4 "LM74700D-Q1" D0008A-MFG 3696.83,887.81 r0 top
U5 "INA185A2IDRLT" DRL0006A 3890.31,2169.82 r0 top
U6 "INA185A2IDRLT" DRL0006A 3878.92,2675.21 r0 top
U7 "INA185A2IDRLT" DRL0006A 4500.52,2672.23 r0 top
U8 "INA185A2IDRLT" DRL0006A 4489.7,2182.36 r0 top
USB1 "629722000214" FP-629722000214_CONN_USB-MFG 99.31,806.46 r270 top
XDS1 "MSP432E401YTPDTR" PDT0128A 917.61,790.57 r180 top
Y1 "X1E0000210179" FP-X1E0000210179_TSX-3225-MFG 1128.92,1528.66 r180 top
Y2 "NX3225GA-16.000M-STD-CRG-1" NDK_NX3225GA 480.69,666.88 r180 top
ZZ1 "This Assembly Note is for PCB labels only" AssemblyNoteLabel 78.04,7760 r0 top
ZZ2 "These assemblies are ESD sensitive, ESD precautions shall be observed." AssemblyNote 83,7642 r0 top
ZZ3 "These assemblies must be clean and free from flux and all contaminants. Use of no clean flux is not acceptable." AssemblyNote 82,7517 r0 top
ZZ4 "These assemblies must comply with workmanship standards IPC-A-610 Class 2, unless otherwise specified." AssemblyNote 82,7372 r0 top

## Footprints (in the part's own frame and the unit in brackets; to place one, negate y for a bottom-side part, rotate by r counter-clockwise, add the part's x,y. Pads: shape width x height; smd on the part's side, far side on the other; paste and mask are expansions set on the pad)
0402 [mm] "0402 from SM-752 data"
  rect 0.8x0.6 smd: 1(-0.6,0) 2(0.6,0)
  silkscreen extent -1.22,-0.52 1.22,0.52, body extent -0.55,-0.3 0.55,0.3, height 0.6
0603 [mm] "0603 from SM-752 data"
  rect 1x0.95 smd: 1(-0.8,0) 2(0.8,0)
  silkscreen extent -1.52,-0.69 1.52,0.69, body extent -0.87,-0.47 0.87,0.47, height 1
0603L [mm] "0603 from SM-752 data"
  rect 0.8x0.85 smd: 1(-0.7,0) 2(0.7,0)
  silkscreen extent -0.07,-0.32 0.07,0.32, body extent -0.87,-0.47 0.87,0.47, height 1
0805_150 [mm] "0805 / 1.5 mm height"
  rect 1.15x1.45 smd: 1(-0.9,0) 2(0.9,0)
  silkscreen extent -0.1,-0.8 0.1,0.8, body extent -1.1,-0.72 1.1,0.72, height 1.5
0805_HV [mil] "0805 with 30mil clearance between pads"
  rect 50x63 smd: 1(-40,0) 2(40,0)
  silkscreen extent -74,-40 74,40, body extent -43,-29 43,29, height 57
1206 [mm] "1206 from SM-752 data"
  rect 1.3x1.85 smd: 1(-1.45,0) 2(1.45,0)
  silkscreen extent -2.4,-1.21 2.4,1.21, body extent -1.7,-0.9 1.7,0.9, height 1.35
1210 [mm] "1210 from SM-752 data"
  rect 1.3x2.7 smd: 1(-1.45,0) 2(1.45,0)
  silkscreen extent -2.32,-1.57 2.32,1.57, body extent -1.7,-1.35 1.7,1.35, height 1.35
AssemblyNote [mil] "Assembly Note"
AssemblyNoteLabel [mil] "Assembly Note for PCB Labels"
CE_Mark_5mm [mil] "Minimum text height for CE Mark"
  silkscreen extent -138,-98 138,98
D0008A-MFG [mm] "Recommended Land Pattern"
  rrect17% 1.55x0.6 smd paste+0 mask+0: 1(-2.7,1.905) 2(-2.7,0.635) 3(-2.7,-0.635) 4(-2.7,-1.905) 5(2.7,-1.905) 6(2.7,-0.635) 7(2.7,0.635) 8(2.7,1.905)
  silkscreen extent -4.17,-2.5 1.5,2.5, body extent -3,-2.45 3,2.45, height 1.75
DCK0005A_N [mm] "SOT353, 5-Leads, Body 2x1.3mm, Pitch 0.65mm, Lead Span 2.1mm, IPC Medium Density"
  rrect25% 0.85x0.4 smd: 1(-1.125,0.65) 2(-1.125,0) 3(-1.125,-0.65) 4(1.125,-0.65) 5(1.125,0.65)
  silkscreen extent -1.48,-1.02 0.55,1.1, body extent -1.14,-1 1.14,1, height 0.95
DGQ0024A-MFG [mm] "Recommended Land Pattern"
  rrect33% 1.45x0.3 smd paste+0 mask+0: 1(-2.2,2.75) 2(-2.2,2.25) 3(-2.2,1.75) 4(-2.2,1.25) 5(-2.2,0.75) 6(-2.2,0.25) 7(-2.2,-0.25) 8(-2.2,-0.75) 9(-2.2,-1.25) 10(-2.2,-1.75) 11(-2.2,-2.25) 12(-2.2,-2.75) 13(2.2,-2.75) 14(2.2,-2.25) 15(2.2,-1.75) 16(2.2,-1.25) 17(2.2,-0.75) 18(2.2,-0.25) 19(2.2,0.25) 20(2.2,0.75) 21(2.2,1.25) 22(2.2,1.75) 23(2.2,2.25) 24(2.2,2.75)
  rrect5% 2.2x6.1 smd paste-1000 mask-1000: 25(0,0)
  silkscreen extent -2.8,-3.42 1.55,3.57, body extent -3.03,-3.35 3.03,3.35, height 0.25
DNK0008A [mm] "SON, 8-Leads, Body 5x6mm"
  rrect39% 0.86x0.51 smd paste-0.05 mask-0.05: 1(-2.82,1.905) 2(-2.82,0.635) 3(-2.82,-0.635) 4(-2.82,-1.905) 5(2.82,-1.905) 6(2.82,-0.635) 7(2.82,0.635) 8(2.82,1.905)
  rrect40% 0.25x0.555 on Top Solder: 9(-0.83,2.372) 9(-0.83,-2.372)
  rrect40% 0.25x0.555 on Top Paste: 9(-0.83,2.372) 9(-0.83,-2.372)
  rrect11% 0.95x1.13 on Top Paste: 9(-0.535,0) 9(-0.535,1.33) 9(-0.535,-1.33) 9(0.615,1.33) 9(0.615,0) 9(0.615,-1.33) 9(1.765,-1.33) 9(1.765,0) 9(1.765,1.33)
  rrect3% 3.58x4 on Top Solder: 9(0.75,0)
  rrect5% 4.34x5.4 smd paste-3 mask-3: 9(1.08,0)
  body extent -3.05,-2.55 3.05,2.55, height 1.06
DRB0008A [mm] "VSON-8"
  rrect32% 0.6x0.31 smd: 1(-1.4,0.975) 2(-1.4,0.325) 3(-1.4,-0.325) 4(-1.4,-0.975) 5(1.4,-0.975) 6(1.4,-0.325) 7(1.4,0.325) 8(1.4,0.975)
  rrect7% 1.5x1.75 smd paste-0.75: 9(0,0)
  Top Layer region: -0.7,-0.875 -0.49,-0.875 -0.471,-0.879 -0.455,-0.89 -0.444,-0.906 -0.44,-0.925 -0.44,-0.925 -0.44,-1.65 -0.436,-1.669 -0.425,-1.685 -0.409,-1.696 -0.39,-1.7 -0.39,-1.7 -0.26,-1.7 -0.241,-1.696 -0.225,-1.685 -0.214,-1.669 -0.21,-1.65 -0.21,-1.65 -0.21,-0.925 -0.206,-0.906 -0.195,-0.89 -0.179,-0.879 -0.16,-0.875 -0.16,-0.875 0.16,-0.875 0.179,-0.879 0.195,-0.89 0.206,-0.906 0.21,-0.925 0.21,-0.925 0.21,-1.65 0.21,-1.65 0.214,-1.669 0.225,-1.685 0.241,-1.696 0.26,-1.7 0.26,-1.7 0.39,-1.7 0.409,-1.696 0.425,-1.685 0.436,-1.669 0.44,-1.65 0.44,-1.65 0.44,-0.925 0.444,-0.906 0.455,-0.89 0.471,-0.879 0.49,-0.875 0.49,-0.875 0.7,-0.875 0.719,-0.871 0.735,-0.86 0.746,-0.844 0.75,-0.825 0.75,-0.825 0.75,0.825 0.746,0.844 0.735,0.86 0.719,0.871 0.7,0.875 0.7,0.875 0.49,0.875 0.471,0.879 0.455,0.89 0.444,0.906 0.44,0.925 0.44,0.925 0.44,1.65 0.436,1.669 0.425,1.685 0.409,1.696 0.39,1.7 0.39,1.7 0.26,1.7 0.241,1.696 0.225,1.685 0.214,1.669 0.21,1.65 0.21,1.65 0.21,1.65 0.21,0.925 0.206,0.906 0.195,0.89 0.179,0.879 0.16,0.875 0.16,0.875 -0.16,0.875 -0.179,0.879 -0.195,0.89 -0.206,0.906 -0.21,0.925 -0.21,0.925 -0.21,1.65 -0.214,1.669 -0.225,1.685 -0.241,1.696 -0.26,1.7 -0.26,1.7 -0.39,1.7 -0.409,1.696 -0.425,1.685 -0.436,1.669 -0.44,1.65 -0.44,1.65 -0.44,0.925 -0.444,0.906 -0.455,0.89 -0.471,0.879 -0.49,0.875 -0.49,0.875 -0.7,0.875 -0.719,0.871 -0.735,0.86 -0.746,0.844 -0.75,0.825 -0.75,0.825 -0.75,-0.825 -0.746,-0.844 -0.735,-0.86 -0.719,-0.871 -0.7,-0.875
  silkscreen extent -1.73,-1.73 1.73,1.73, body extent -1.5,-1.5 1.5,1.5, height 0.77
DRL0006A [mm] "SOTFL, 6-Flat Leads, Body 1.2x1.6x0.6mm, Pitch 0.5mm, TI recommended"
  rrect33% 0.67x0.3 smd: 1(-0.74,0.5) 2(-0.74,0) 3(-0.74,-0.5) 4(0.74,-0.5) 5(0.74,0) 6(0.74,0.5)
  silkscreen extent -0.9,-0.95 0.5,0.95, body extent -0.8,-0.8 0.8,0.8, height 0.61
DRV0006A [mm] "SON, 6-Leads, Body 2x2mm, Pitch 0.65mm, Thermal Pad 1.6x1mm, TI Recommended"
  rrect33% 0.45x0.3 smd: 1(-0.975,-0.65) 2(-0.975,0) 3(-0.975,0.65) 4(0.975,0.65) 5(0.975,0) 6(0.975,-0.65)
  rrect14% 1x0.7 on Top Paste: 7(0,0.45) 7(0,-0.45)
  rrect10% 1x1.6 smd paste-0.5: 7(0,0)
  silkscreen extent -1.05,-1.2 1.05,1.2, body extent -1.05,-1.05 1.05,1.05, height 0.81
DRY0006A [mm] "USON-6"
  rrect67% 0.45x0.3 smd paste-0.05 mask-0.05: 1(-0.275,0.5)
  rrect67% 0.4x0.3 smd paste-0.05 mask-0.05: 2(-0.3,0) 3(-0.3,-0.5) 4(0.3,-0.5) 5(0.3,0) 6(0.3,0.5)
  body extent -0.5,-0.72 0.5,0.73, height 0.58
FCC_disclaimer [mil]
Fiducial10-20 [mm]
  round 1 smd mask+0.5: 1(0,0)
  Top Layer keep-out circle w1.178: c0,0 r0.5
FP-61301221121_HDR12-MFG [mm]
  rrect6% 1.7x1.7 hole 1.1 paste-1000 mask+0: 1(-6.35,1.27)
  round 1.7 hole 1.1 paste-1000 mask+0: 2(-6.35,-1.27) 3(-3.81,1.27) 4(-3.81,-1.27) 5(-1.27,1.27) 6(-1.27,-1.27) 7(1.27,1.27) 8(1.27,-1.27) 9(3.81,1.27) 10(3.81,-1.27) 11(6.35,1.27) 12(6.35,-1.27)
  silkscreen extent -7.77,-2.62 7.77,3.22, body extent -7.62,-2.54 7.62,2.54, height 5.54
FP-61301421121_HDR14-MFG#1 [mm]
  rrect6% 1.7x1.7 hole 1.1 paste-1000 mask+0: 1(-7.62,1.27)
  round 1.7 hole 1.1 paste-1000 mask+0: 2(-7.62,-1.27) 3(-5.08,1.27) 4(-5.08,-1.27) 5(-2.54,1.27) 6(-2.54,-1.27) 7(0,1.27) 8(0,-1.27) 9(2.54,1.27) 10(2.54,-1.27) 11(5.08,1.27) 12(5.08,-1.27) 13(7.62,1.27) 14(7.62,-1.27)
  silkscreen extent -9.76,-2.62 9.04,2.62, body extent -8.89,-2.54 8.89,2.54, height 8.89
FP-61301421121_HDR14-MFG#2 [mm]
  rrect6% 1.7x1.7 hole 1.1 paste-1000 mask+0: 1(-7.62,-1.27)
  round 1.7 hole 1.1 paste-1000 mask+0: 2(-7.62,1.27) 3(-5.08,-1.27) 4(-5.08,1.27) 5(-2.54,-1.27) 6(-2.54,1.27) 7(0,-1.27) 8(0,1.27) 9(2.54,-1.27) 10(2.54,1.27) 11(5.08,-1.27) 12(5.08,1.27) 13(7.62,-1.27) 14(7.62,1.27)
  silkscreen extent -9.76,-2.62 9.04,2.62, body extent -9.14,-2.72 9.14,2.72, height 0.25
FP-61301621121_HDR16-MFG [mm] "Recommended Land Pattern"
  rrect6% 1.7x1.7 hole 1.1 paste-2539.97 mask+0: 1(-8.89,-1.27)
  round 1.7 hole 1.1 paste-2539.97 mask+0: 2(-8.89,1.27) 3(-6.35,-1.27) 4(-6.35,1.27) 5(-3.81,-1.27) 6(-3.81,1.27) 7(-1.27,-1.27) 8(-1.27,1.27) 9(1.27,-1.27) 10(1.27,1.27) 11(3.81,-1.27) 12(3.81,1.27) 13(6.35,-1.27) 14(6.35,1.27) 15(8.89,-1.27) 16(8.89,1.27)
  silkscreen extent -10.31,-3.22 10.31,2.62, body extent -10.16,-2.54 10.16,2.54, height 8.89
FP-430481025816_SMT_SW_6MM2_6MM2-MFG [mm]
  rrect7% 2x1.4 smd paste+0 mask+0: 1(-3.5,2) 2(3.5,2) 3(-3.5,-2) 4(3.5,-2)
  silkscreen extent -5.18,-3.2 3.2,3.2, body extent -4.6,-3.3 4.6,3.3, height 0.25
FP-580060720008_0805-MFG [mm]
  rrect10% 1x1.36 smd paste+0 mask+0: 1(-0.9,0) 2(0.9,0)
  silkscreen extent 0,-0.68 0,0.68, body extent -1.5,-0.8 1.5,0.8, height 0.25
FP-629722000214_CONN_USB-MFG [mm]
  rrect100% 1x2.1 hole 1.7 slot 0.6 at 0 deg paste-1000 mask+0: 1(-4.32,3.035) 2(4.32,3.035)
  rrect100% 1x1.8 hole 1.4 slot 0.6 at 0 deg paste-1000 mask+0: 3(-4.32,-1.145) 4(4.32,-1.145)
  rrect17% 0.6x1.15 smd paste+0 mask+0: A1-B12(-3.2,3.6) A4-B9(-2.4,3.6) A9-B4(2.4,3.6) A12-B1(3.2,3.6)
  rrect33% 0.3x1.15 smd paste+0 mask+0: A5(-1.25,3.6) A6(-0.25,3.6) A7(0.25,3.6) A8(1.25,3.6) B5(1.75,3.6) B6(0.75,3.6) B7(-0.75,3.6) B8(-1.75,3.6)
  round 0.65 hole 0.65 unplated paste-1000 mask+0: ""(-2.89,2.535) ""(2.89,2.535)
  silkscreen extent -4.89,0.13 4.89,4.86, body extent -4.99,-3.97 4.99,4.28, height 0.25
FP-691236510002_HHR2-MFG [mm]
  rrect4% 2.3x2.3 hole 1.5 paste-1000 mask+0: 1(-2.24,-0.175)
  round 2.3 hole 1.5 paste-1000 mask+0: 2(2.84,-0.175)
  silkscreen extent -5.48,-6.45 5.48,5.72, body extent -5.58,-5.82 5.58,5.82, height 0.25
FP-885012005057_0402-MFG [mm]
  rrect20% 0.5x0.5 smd paste+0 mask+0: 1(-0.5,0) 2(0.5,0)
  silkscreen extent -0.5,-0.63 0.5,0.63, body extent -0.85,-0.38 0.85,0.38, height 0.25
FP-885012206065_0603-MFG [mm]
  rrect13% 0.8x0.8 smd paste+0 mask+0: 1(-0.75,0) 2(0.75,0)
  silkscreen extent -0.85,-0.77 0.85,0.77, body extent -1.25,-0.55 1.25,0.55, height 0.25
FP-885012206095_0603-MFG [mm]
  rrect13% 0.8x0.8 smd paste+0 mask+0: 1(-0.75,0) 2(0.75,0)
  silkscreen extent -0.85,-0.77 0.85,0.77, body extent -1.25,-0.55 1.25,0.55, height 0.25
FP-885012206120_0603-MFG [mm]
  rrect13% 0.8x0.8 smd paste+0 mask+0: 1(-0.75,0) 2(0.75,0)
  silkscreen extent -0.85,-0.77 0.85,0.77, body extent -0.8,-0.4 0.8,0.4, height 0.87
FP-885012206126_0603-MFG [mm]
  rrect13% 0.8x0.8 smd paste+0 mask+0: 1(-0.75,0) 2(0.75,0)
  silkscreen extent -0.8,-0.77 0.8,0.77, body extent -1.25,-0.58 1.25,0.58, height 0.25
FP-885012209069_1210-MFG [mm]
  rrect11% 0.9x2.5 smd paste+0 mask+0: 1(-1.55,0) 2(1.55,0)
  silkscreen extent -0.72,-1.4 0.72,1.4, body extent -2.1,-1.5 2.1,1.5, height 0.25
FP-RBS-37BK_BUMPER_CYLI-MFG [mil]
  silkscreen extent -370,-370 370,370, body extent -360,-360 360,360, height 579
FP-RCC040247K0FKED_0402-MFG [mm]
  rrect17% 0.6x0.6 smd paste+0 mask+0: 1(-0.525,0) 2(0.525,0)
  silkscreen extent -0.53,-0.68 0.52,0.67, body extent -0.92,-0.4 0.92,0.4, height 0.25
FP-SOD323F-MFG [mm]
  rect 0.6x0.6 smd paste-1000 mask+0: 1(-1.1,0) 2(1.1,0)
  silkscreen extent -2.08,-0.67 0.43,0.67, body extent -1.53,-0.82 1.53,0.82, height 0.25
FP-X1E0000210179_TSX-3225-MFG [mm]
  rrect9% 1.4x1.15 smd paste+0 mask+0: 1(-1.1,-0.8) 2(1.1,-0.8) 3(1.1,0.8) 4(-1.1,0.8)
  silkscreen extent -1.22,-2.05 0,1.33, body extent -1.6,-1.25 1.6,1.25, height 0.6
Harwin_D3082-05 [mm] "Shorting Plug, 10.16mm spacing, TH"
  round 1.8 hole 1.3: 1(-5.08,0) 2(5.08,0)
  silkscreen extent -3.9,-0.53 3.9,0.53, body extent -5.6,-0.52 5.61,0.52, height 6.63
IEC_Caution_Small [mil]
  silkscreen extent -107,-93 107,92
IEC_HotSurface_Small [mil]
  silkscreen extent -107,-93 107,92
Keystone5002 [mil] "For Keystone 500x miniature loop terminals"
  round 80 hole 40: 1(0,0)
  silkscreen extent -52,-52 52,52, body extent -49,-49 49,49, height 182
Keystone5010 [mil] "Keystone Multipurpose loops"
  round 87 hole 63: 1(0,0)
  silkscreen extent -70,-70 70,70, body extent -63,-63 63,62, height 319
Keystone5011 [mil] "Keystone Multipurpose loops"
  round 87 hole 63: 1(0,0)
  silkscreen extent -70,-70 70,70, body extent -63,-63 63,62, height 319
Keystone5012 [mil] "Keystone Multipurpose loops"
  round 87 hole 63: 1(0,0)
  silkscreen extent -70,-70 70,70, body extent -63,-63 63,62, height 319
Keystone5013 [mil] "Keystone Multipurpose loops"
  round 87 hole 63: 1(0,0)
  silkscreen extent -70,-70 70,70, body extent -63,-63 63,62, height 319
LED_LTST-C190 [mm] "Lite-On"
  rect 0.8x0.8 smd: 1(-0.75,0) 2(0.75,0)
  silkscreen extent -1.1,-0.8 1.8,0.8, body extent -0.85,-0.45 0.85,0.45, height 0.9
LED_LTST-C190_Red [mm] "Lite-On"
  rect 0.8x0.8 smd: 1(-0.75,0) 2(0.75,0)
  silkscreen extent -1.1,-0.8 1.8,0.8, body extent -0.85,-0.45 0.85,0.45, height 0.9
NDK_NX3225GA [mm] "NDK"
  rect 1.2x1.4 smd: 1(-0.8,1.1) 2(-0.8,-1.1) 3(0.8,-1.1) 4(0.8,1.1)
  silkscreen extent -1.9,-0.1 1.4,2, body extent -1.3,-1.65 1.3,1.65, height 0.9
ONSC-SOT-23-3-318-08_V [mm] "SOT23, 3-Leads, Body 2.92x1.3mm, Pitch 0.95mm"
  rect 0.9x0.8 smd: 1(-1,0.95) 2(-1,-0.95) 3(1,0)
  silkscreen extent -1.12,-1.46 0.65,2.02, body extent -0.65,-1.46 0.65,1.46, height 1.11
PDT0128A [mm] "Thin QFP, 128-Leads, Body 14x14mm, Pitch 0.4mm"
  oval 1.4x0.2 smd: 1(-7.7,6.2) 2(-7.7,5.8) 3(-7.7,5.4) 4(-7.7,5) 5(-7.7,4.6) 6(-7.7,4.2) 7(-7.7,3.8) 8(-7.7,3.4) 9(-7.7,3) 10(-7.7,2.6) 11(-7.7,2.2) 12(-7.7,1.8) 13(-7.7,1.4) 14(-7.7,1) 15(-7.7,0.6) 16(-7.7,0.2) 17(-7.7,-0.2) 18(-7.7,-0.6) 19(-7.7,-1) 20(-7.7,-1.4) 21(-7.7,-1.8) 22(-7.7,-2.2) 23(-7.7,-2.6) 24(-7.7,-3) 25(-7.7,-3.4) 26(-7.7,-3.8) 27(-7.7,-4.2) 28(-7.7,-4.6) 29(-7.7,-5) 30(-7.7,-5.4) 31(-7.7,-5.8) 32(-7.7,-6.2) 65(7.7,-6.2) 66(7.7,-5.8) 67(7.7,-5.4) 68(7.7,-5) 69(7.7,-4.6) 70(7.7,-4.2) 71(7.7,-3.8) 72(7.7,-3.4) 73(7.7,-3) 74(7.7,-2.6) 75(7.7,-2.2) 76(7.7,-1.8) 77(7.7,-1.4) 78(7.7,-1) 79(7.7,-0.6) 80(7.7,-0.2) 81(7.7,0.2) 82(7.7,0.6) 83(7.7,1) 84(7.7,1.4) 85(7.7,1.8) 86(7.7,2.2) 87(7.7,2.6) 88(7.7,3) 89(7.7,3.4) 90(7.7,3.8) 91(7.7,4.2) 92(7.7,4.6) 93(7.7,5) 94(7.7,5.4) 95(7.7,5.8) 96(7.7,6.2)
  oval 0.2x1.4 smd: 33(-6.2,-7.7) 34(-5.8,-7.7) 35(-5.4,-7.7) 36(-5,-7.7) 37(-4.6,-7.7) 38(-4.2,-7.7) 39(-3.8,-7.7) 40(-3.4,-7.7) 41(-3,-7.7) 42(-2.6,-7.7) 43(-2.2,-7.7) 44(-1.8,-7.7) 45(-1.4,-7.7) 46(-1,-7.7) 47(-0.6,-7.7) 48(-0.2,-7.7) 49(0.2,-7.7) 50(0.6,-7.7) 51(1,-7.7) 52(1.4,-7.7) 53(1.8,-7.7) 54(2.2,-7.7) 55(2.6,-7.7) 56(3,-7.7) 57(3.4,-7.7) 58(3.8,-7.7) 59(4.2,-7.7) 60(4.6,-7.7) 61(5,-7.7) 62(5.4,-7.7) 63(5.8,-7.7) 64(6.2,-7.7) 97(6.2,7.7) 98(5.8,7.7) 99(5.4,7.7) 100(5,7.7) 101(4.6,7.7) 102(4.2,7.7) 103(3.8,7.7) 104(3.4,7.7) 105(3,7.7) 106(2.6,7.7) 107(2.2,7.7) 108(1.8,7.7) 109(1.4,7.7) 110(1,7.7) 111(0.6,7.7) 112(0.2,7.7) 113(-0.2,7.7) 114(-0.6,7.7) 115(-1,7.7) 116(-1.4,7.7) 117(-1.8,7.7) 118(-2.2,7.7) 119(-2.6,7.7) 120(-3,7.7) 121(-3.4,7.7) 122(-3.8,7.7) 123(-4.2,7.7) 124(-4.6,7.7) 125(-5,7.7) 126(-5.4,7.7) 127(-5.8,7.7) 128(-6.2,7.7)
  silkscreen extent -7.7,-6.3 6.3,6.99, body extent -8,-8 8,8, height 1.07
PM0064A-MFG [mm]
  rrect33% 1.5x0.3 smd paste+0 mask+0: 1(-5.7,3.75) 2(-5.7,3.25) 3(-5.7,2.75) 4(-5.7,2.25) 5(-5.7,1.75) 6(-5.7,1.25) 7(-5.7,0.75) 8(-5.7,0.25) 9(-5.7,-0.25) 10(-5.7,-0.75) 11(-5.7,-1.25) 12(-5.7,-1.75) 13(-5.7,-2.25) 14(-5.7,-2.75) 15(-5.7,-3.25) 16(-5.7,-3.75) 33(5.7,-3.75) 34(5.7,-3.25) 35(5.7,-2.75) 36(5.7,-2.25) 37(5.7,-1.75) 38(5.7,-1.25) 39(5.7,-0.75) 40(5.7,-0.25) 41(5.7,0.25) 42(5.7,0.75) 43(5.7,1.25) 44(5.7,1.75) 45(5.7,2.25) 46(5.7,2.75) 47(5.7,3.25) 48(5.7,3.75)
  rrect33% 0.3x1.5 smd paste+0 mask+0: 17(-3.75,-5.7) 18(-3.25,-5.7) 19(-2.75,-5.7) 20(-2.25,-5.7) 21(-1.75,-5.7) 22(-1.25,-5.7) 23(-0.75,-5.7) 24(-0.25,-5.7) 25(0.25,-5.7) 26(0.75,-5.7) 27(1.25,-5.7) 28(1.75,-5.7) 29(2.25,-5.7) 30(2.75,-5.7) 31(3.25,-5.7) 32(3.75,-5.7) 49(3.75,5.7) 50(3.25,5.7) 51(2.75,5.7) 52(2.25,5.7) 53(1.75,5.7) 54(1.25,5.7) 55(0.75,5.7) 56(0.25,5.7) 57(-0.25,5.7) 58(-0.75,5.7) 59(-1.25,5.7) 60(-1.75,5.7) 61(-2.25,5.7) 62(-2.75,5.7) 63(-3.25,5.7) 64(-3.75,5.7)
  silkscreen extent -7.12,-5.1 5.1,5.1, body extent -6.55,-6.55 6.55,6.55, height 0.25
SMB-Bi [mil] "Molded Diode, 2-Leads, Body 5.4x3.6mm, IPC Medium Density, based on OnSemi component dimensions"
  rect 85x107.99 smd: 1(-87.01,0) 2(87.01,0)
  silkscreen extent -125,-79 125,79, body extent -104,-73 104,73, height 89
SMC_Bi [mil] "SMC, no polarity mark"
  rect 110x150 smd: 1(-140.49,0) 2(140.49,0)
  body extent -156,-116 156,116, height 92
TI_Stacked_Overlay_Small [mil]
  silkscreen extent -418,-98 418,98
TP_SM_1MM [mm] "1mm Test Point, SMT"
  round 1 smd paste-0.5: 1(0,0)
WCAP-ATUL_D10H12.5 [mm] "Aluminum Electrolytic Capacitors, 10x12.5mm"
  rrect50% 1.4x1.4 hole 0.9: 1(2.5,0)
  round 1.4 hole 0.9: 2(-2.5,0)
  silkscreen extent -5.25,-5.25 5.25,5.25, body extent -4.99,-5 5,5, height 12.81
WCAP-ATUL_D10H20 [mm] "Aluminum Electrolytic Capacitors, 10x20mm"
  rrect50% 1.4x1.4 hole 0.9: 1(2.5,0)
  round 1.4 hole 0.9: 2(-2.5,0)
  silkscreen extent -5.25,-5.25 5.25,5.25, body extent -4.99,-5 4.99,5, height 20.31
WCAP-CSGP_0603_L1.6W0.8H0.8_Reflow [mm] "Ceramic Capacitors, body 1.6x0.8mm"
  rect 0.8x0.8 smd: 1(-0.75,0) 2(0.75,0)
  body extent -0.8,-0.4 0.8,0.4, height 0.8
WCAP-CSGP_0805_L2W1.25H0.8_Reflow [mm] "Ceramic Capacitors, body 2x1.25mm"
  rect 0.9x1.3 smd: 1(-0.95,0) 2(0.95,0)
  body extent -1,-0.62 1,0.63, height 0.8
WCAP-CSST_1210_L3.2W2.5H2.5 [mm] "Soft Termination MLCC, body 3.20x2.50mm"
  rect 0.9x2.5 smd: 1(-1.55,0) 2(1.55,0)
  silkscreen extent -0.8,-1.5 0.8,1.5, body extent -1.6,-1.25 1.6,1.25, height 2.5
WE-HCC_1210 [mm] "WURTH"
  rect 2.9x5.4 smd: 1(-4.95,0) 2(4.95,0)
  silkscreen extent -6,-5.9 6,5.9, body extent -6,-5.85 6,5.85, height 10
WEEE_Minimum [mil] "WEEElie bin"
  silkscreen extent -95,-172 99,104
WL-SMCW_GREEN [mm] "WURTH"
  rect 0.8x0.8 smd: 1(-0.8,0) 2(0.8,0)
  silkscreen extent -1.9,-0.8 1.2,0.8, body extent -0.85,-0.45 0.85,0.45, height 0.8
WL-SMCW_RED [mm] "WURTH"
  rect 0.8x0.8 smd: 1(-0.8,0) 2(0.8,0)
  silkscreen extent -1.9,-0.8 1.2,0.8, body extent -0.85,-0.45 0.85,0.45, height 0.8
Wurth_60900213421 [mil] "Shunt, 2.54mm, Black"
  round 1 on Mech3: 0(0,0)
  body extent -98,-48 98,48, height 338
WURTH_61300211121 [mm] "Header, 2.54mm, 2x1, TH"
  rrect50% 1.65x1.65 hole 1.15: 1(-1.27,0)
  round 1.65 hole 1.15: 2(1.27,0)
  body extent -2.54,-1.27 2.54,1.27, height 8.54
WURTH_61300411121 [mm] "Header, 2.54mm, 4x1, TH"
  rrect50% 1.65x1.65 hole 1.15: 1(-3.81,0)
  round 1.65 hole 1.15: 2(-1.27,0) 3(1.27,0) 4(3.81,0)
  body extent -5.08,-1.27 5.08,1.27, height 8.54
